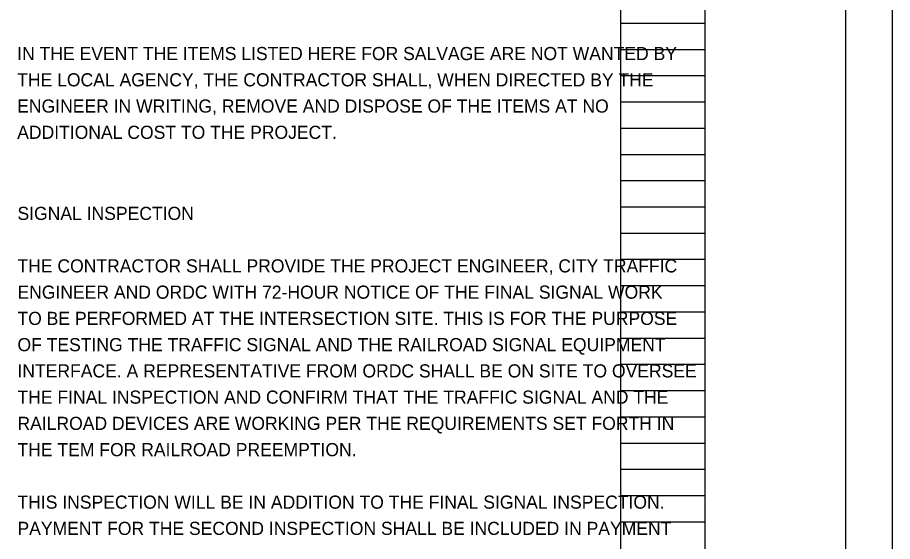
# Model space of a CAD drawing. Extents: x 0 to 34, y 0 to 22.
# Drawn here: x 24.66 to 34, y 5.53 to 11.12 of the extents above; entities that cross this region are included whole.
import ezdxf

# ---------------------------------------------------------------- set-up
doc = ezdxf.new("R2010")
doc.units = 0
for name, color, linetype in [('SH_Border', 7, 'Continuous'), ('SH_Cut_Line', 7, 'Continuous'), ('SH_Data', 7, 'Continuous'), ('SH_Text', 7, 'Continuous')]:
    doc.layers.add(name, color=color, linetype=linetype)

msp = doc.modelspace()

# ---------------------------------------------------------------- linework, layer by layer
at = {"layer": 'SH_Border'}
msp.add_line((32, 0.5), (32, 21.5), dxfattribs=at)
msp.add_lwpolyline([(1.5, 21.5), (33.5, 21.5), (33.5, 0.5), (1.5, 0.5)], close=True, dxfattribs=at)
at = {"layer": 'SH_Cut_Line'}
msp.add_lwpolyline([(0, 0), (34, 0), (34, 22), (0, 22)], close=True, dxfattribs=at)
at = {"layer": 'SH_Data'}
for p, q in [((31.1, 0.98), (31.1, 21.14)), ((32, 0.98), (32, 21.14)), ((31.1, 11.06), (32, 11.06)), ((31.1, 10.78), (32, 10.78)), ((31.1, 10.5), (32, 10.5)), ((31.1, 10.22), (32, 10.22)), ((31.1, 9.94), (32, 9.94)), ((31.1, 9.66), (32, 9.66)), ((31.1, 9.38), (32, 9.38)), ((31.1, 9.1), (32, 9.1)), ((31.1, 8.82), (32, 8.82)), ((31.1, 8.54), (32, 8.54)), ((31.1, 8.26), (32, 8.26)), ((31.1, 7.98), (32, 7.98)), ((31.1, 7.7), (32, 7.7)), ((31.1, 7.42), (32, 7.42)), ((31.1, 7.14), (32, 7.14)), ((31.1, 6.86), (32, 6.86)), ((31.1, 6.58), (32, 6.58)), ((31.1, 6.3), (32, 6.3)), ((31.1, 6.02), (32, 6.02)), ((31.1, 5.74), (32, 5.74))]:
    msp.add_line(p, q, dxfattribs=at)

# ---------------------------------------------------------------- texts
at = {"layer": 'SH_Text'}
for s, p in [('IN THE EVENT THE ITEMS LISTED HERE FOR SALVAGE ARE NOT WANTED BY ', (24.6572, 10.6652)), ('THE LOCAL AGENCY, THE CONTRACTOR SHALL, WHEN DIRECTED BY THE ', (24.6572, 10.3852)), ('ENGINEER IN WRITING, REMOVE AND DISPOSE OF THE ITEMS AT NO ', (24.6572, 10.1052)), ('ADDITIONAL COST TO THE PROJECT. ', (24.6572, 9.8252)), ('SIGNAL INSPECTION', (24.66, 8.96)), ('THE CONTRACTOR SHALL PROVIDE THE PROJECT ENGINEER, CITY TRAFFIC ', (24.66, 8.4)), ('ENGINEER AND ORDC WITH 72-HOUR NOTICE OF THE FINAL SIGNAL WORK ', (24.66, 8.12)), ('TO BE PERFORMED AT THE INTERSECTION SITE. THIS IS FOR THE PURPOSE ', (24.66, 7.84)), ('OF TESTING THE TRAFFIC SIGNAL AND THE RAILROAD SIGNAL EQUIPMENT ', (24.66, 7.56)), ('INTERFACE. A REPRESENTATIVE FROM ORDC SHALL BE ON SITE TO OVERSEE ', (24.66, 7.28)), ('THE FINAL INSPECTION AND CONFIRM THAT THE TRAFFIC SIGNAL AND THE ', (24.66, 7)), ('RAILROAD DEVICES ARE WORKING PER THE REQUIREMENTS SET FORTH IN ', (24.66, 6.72)), ('THE TEM FOR RAILROAD PREEMPTION.', (24.66, 6.44)), ('THIS INSPECTION WILL BE IN ADDITION TO THE FINAL SIGNAL INSPECTION. ', (24.66, 5.88)), ('PAYMENT FOR THE SECOND INSPECTION SHALL BE INCLUDED IN PAYMENT ', (24.66, 5.6))]:
    msp.add_text(s, height=0.14, dxfattribs=at).set_placement(p)

doc.saveas('drawing.dxf')
